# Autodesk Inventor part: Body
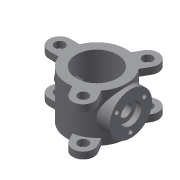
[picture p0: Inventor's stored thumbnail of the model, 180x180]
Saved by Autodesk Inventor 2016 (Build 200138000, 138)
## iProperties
Created: 2011-04
Part Number: Body
Material: Generic
Document SubType Name: Modeling
Designer: Dell
Density: 1 g/cm^3
Appearance: Default
Author: Dell
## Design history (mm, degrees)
sketch "Sketch1"
  geometry: 1 further point
sketch "Sketch2"
  geometry: C1 r 97 at (0, 0); C2 r 140 at (0, 0); 1 further point
  constraints: 2 centre point, 1 coincident
  dimensions: "d0" = 194 diameter of C1; "d1" = 280 diameter of C2
extrude "Extrusion1" new body sketch "Sketch2" stored distance "d2" = 225; taper "d3" = 0 deg
workplane "Work Plane1"
sketch "Sketch3"
  geometry: L1 (-140, 112.5)-(140, 112.5) reference; C1 r 100 at (0, 0); 1 further point
  constraints: 1 centre point, 1 coincident
  dimensions: "d5" = 200 diameter of C1; "d7" = 112.5 distance from line of point (0, 0) L1 (derived)
extrude "Extrusion2" join sketch "Sketch3" stored distance "d8" = 225; taper "d9" = 0 deg
hole "Hole1" diameter "d12" = 56; stored, may be unused: countersink angle "d16" = 90 deg, drill point angle "d18" = 118 deg; dims "d13" = 6, "d14" = 100, "d15" = 25, "d17" = 428.75, "d39" = 10, "d40" = 10
workplane "Work Plane2"
sketch "Sketch4"
  geometry: C1 r 37.5 at (0, 0); C2 r 28 at (0, 0); 1 further point
  constraints: 2 centre point, 1 coincident
  dimensions: "d20" = 75 diameter of C1; "d37" = 56 diameter of C2
sketch "Sketch5"
  geometry: L1 (130.767, -50)-(175, -50); L2 (175, 50)-(130.767, 50); C1 r 23.5 at (175, 0); A1 r 50 centre (175, 0) between (175, -50) and (175, 50); A2 r 140 centre (0, 0) between (130.767, -50) and (130.767, 50); 1 further point
  constraints: 4 end point, 4 point on circle, 3 centre point, 2 coincident
  dimensions: "d29" = 50 radius of A1 (derived); "d30" = 47 diameter of C1 (derived); "d31" = 175 distance of A1.centre point (0, 0)
extrude "Extrusion4" join sketch "Sketch5" distance "d32" = 32; taper "d33" = 0 deg
pattern_circular "Circular Pattern1" dims angle "d35" = 360 deg
mirror "Mirror1"
extrude "Extrusion5" join sketch "Sketch4" stored distance "d38" = 32; taper "d41" = 0 deg; dims "d13" = 6
sketch "Sketch6"
  geometry: C1 r 50 at (0, 0); C2 r 100 at (0, 0); 3 further points
  constraints: 2 centre point, 4 other
  dimensions: "d44" = 75 distance of point (75, 0) C1.centre; "d45" = 360 deg dimension on C1.centre point (75, 0) (derived)
hole "Hole2" sketch "Sketch6" at (-37.5, 64.952) diameter "d46" = 20.3; stored, may be unused: countersink angle "d50" = 90 deg, drill point angle "d52" = 118 deg; dims "d47" = 6, "d48" = 4, "d49" = 2, "d51" = 15
pattern_circular "Circular Pattern2" dims angle "d54" = 360 deg
body "Solid1"
other parameters: "d19" = -325
